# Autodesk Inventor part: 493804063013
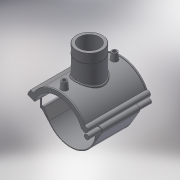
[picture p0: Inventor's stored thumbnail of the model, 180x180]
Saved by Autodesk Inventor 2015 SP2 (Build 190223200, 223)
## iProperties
Created: 2017-07
Part Number: 493804063013
Material: Generic
Description: PLASSON TRANSITION SADDLE 63-1.1/4"
Document SubType Name: Modeling
Designer: KIM
Density: 1 g/cm^3
Appearance: Default
Author: KIM
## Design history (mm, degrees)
derived "493804.ipt"
feature "Solid1::493804.ipt"
tag "TaggingFeature1"
body "Solid1"
other parameters: "d_" = 63, "H_" = 53, "L_" = 118, "d_t" = 6, "G_" = 38.952, "d148" = 0.945, "d160" = 0.945, "d169" = 2.1, "d192" = 4.2, "d0" = 63, "d1" = 78.75, "d3" = 15.75, "d4" = 118, "d5" = 0, "d6" = 0.1, "d8" = 0, "d19" = 6, "d20" = 6, "d21" = 70.8, "d23" = 0, "d24" = 35.4, "d26" = 0, "d27" = 3, "d28" = 3, "d29" = 3, "d30" = 21, "d31" = 6, "d32" = 0, "d33" = 0, "d34" = 0.6, "d40" = 40.95, "d41" = 54.5328, "d43" = 0, "d45" = 0, "d47" = 92.375, "d48" = 50.6376, "d50" = 0, "d70" = 15, "d72" = 0, "d73" = 6, "d75" = 5, "d76" = 0, "d77" = 3.15, "d78" = 61.5, "d79" = 15, "d80" = 47.2, "d82" = 5 deg, "d84" = 4, "d85" = 14, "d86" = 0, "d87" = 3, "d88" = 0, "d89" = 1, "d90" = 1, "d91" = 94.4, "d92" = 0, "d93" = 0.5, "d94" = 33.15789, "d96" = 80.325, "d97" = 2.36, "d98" = 0, "d102" = 1.16856, "d103" = 38.952, "d104" = 31.8, "d105" = 0, "d106" = 31.1616, "d108" = 0, "d109" = -17.66667, "d111" = 0.5, "d112" = 0.5, "d113" = 0, "d114" = 0.5, "d117" = 0.38952, "d120" = 140 deg, "d121" = 24.228, "d122" = 20 deg, "d123" = 157.5, "d124" = 47.25, "d126" = 0, "d143" = 64.89, "d145" = 12.11538, "d149" = 0.945, "d150" = 13.32692, "d153" = 118, "d154" = 0, "d156" = 39.375, "d157" = 160 deg, "d159" = 3.15, "d161" = 0.945, "d162" = 70.8, "d163" = 0, "d164" = 31.5, "d167" = 6.3, "d168" = 38.41463, "d170" = 2.1, "d172" = 0, "d173" = 1, "d175" = 31.5, "d176" = 20 deg, "d177" = 4.41, "d178" = 15.75, "d180" = 0, "d183" = 6.3, "d184" = 3.528, "d185" = 38.35, "d186" = 38.35, "d187" = 39.375, "d188" = 4.725, "d189" = 4.41, "d190" = 0, "d191" = 47.25, "d193" = 4.2, "d194" = 2.95, "d195" = 90 deg, "d197" = 0, "d199" = 0
